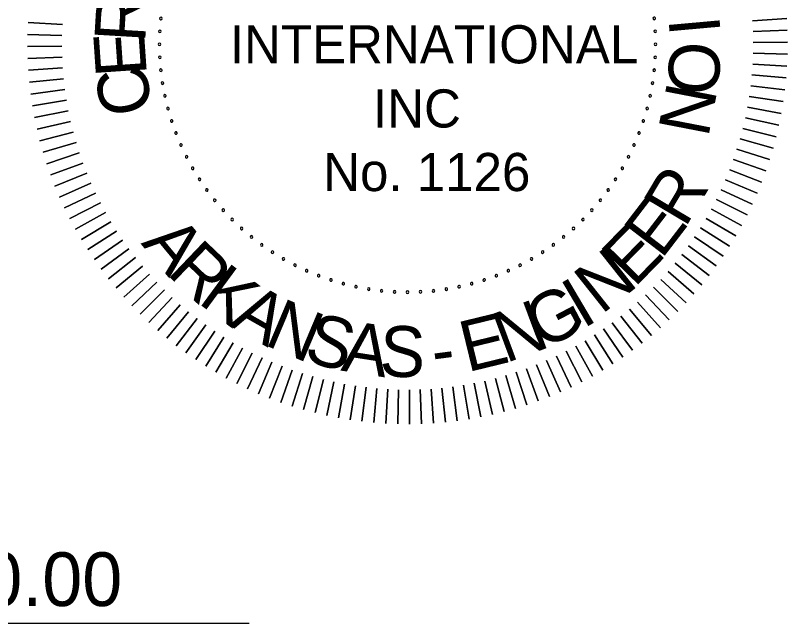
# Model space of a CAD drawing. Extents: x 172 to 3385, y 73 to 2074.
# Drawn here: x 2775.5 to 3028.3, y 337.6 to 536.9 of the extents above; entities that cross this region are included whole.
import ezdxf

# ---------------------------------------------------------------- set-up
doc = ezdxf.new("R2010")
doc.units = 0
doc.layers.add('G-ANNO-TEXT', color=7, linetype='Continuous')
doc.layers.add('R_Border', color=7, linetype='Continuous')

msp = doc.modelspace()

# ---------------------------------------------------------------- linework, layer by layer
at = {"layer": 'G-ANNO-TEXT'}
for points in [[(2790.84, 533.89), (2779.63, 534.53)], [(2779.63, 534.53), (2790.84, 533.89)], [(3028.02, 535.92), (3016.82, 535.15)], [(3016.82, 535.15), (3028.02, 535.92)], [(3028.23, 532.01), (3017.01, 531.6)], [(3017.01, 531.6), (3028.23, 532.01)], [(2790.69, 530.34), (2779.47, 530.63)], [(2779.47, 530.63), (2790.69, 530.34)], [(2790.65, 526.78), (2779.43, 526.72)], [(2779.43, 526.72), (2790.65, 526.78)], [(3028.31, 528.1), (3017.09, 528.04)], [(3017.09, 528.04), (3028.31, 528.1)], [(3028.27, 524.2), (3017.05, 524.49)], [(3017.05, 524.49), (3028.27, 524.2)], [(2790.73, 523.22), (2779.51, 522.81)], [(2779.51, 522.81), (2790.73, 523.22)], [(3028.11, 520.29), (3016.9, 520.93)], [(3016.9, 520.93), (3028.11, 520.29)], [(2790.92, 519.67), (2779.72, 518.91)], [(2779.72, 518.91), (2790.92, 519.67)], [(2791.21, 516.13), (2780.05, 515.01)], [(2780.05, 515.01), (2791.21, 516.13)], [(3027.82, 516.39), (3016.64, 517.38)], [(3016.64, 517.38), (3027.82, 516.39)], [(3027.41, 512.5), (3016.27, 513.85)], [(3016.27, 513.85), (3027.41, 512.5)], [(2791.62, 512.6), (2780.5, 511.13)], [(2780.5, 511.13), (2791.62, 512.6)], [(2792.15, 509.08), (2781.07, 507.26)], [(2781.07, 507.26), (2792.15, 509.08)], [(3026.89, 508.63), (3015.79, 510.32)], [(3015.79, 510.32), (3026.89, 508.63)], [(3026.23, 504.77), (3015.2, 506.82)], [(3015.2, 506.82), (3026.23, 504.77)], [(2792.78, 505.58), (2781.76, 503.41)], [(2781.76, 503.41), (2792.78, 505.58)], [(3025.46, 500.94), (3014.5, 503.33)], [(3014.5, 503.33), (3025.46, 500.94)], [(2793.52, 502.1), (2782.58, 499.59)], [(2782.58, 499.59), (2793.52, 502.1)], [(2794.37, 498.64), (2783.51, 495.79)], [(2783.51, 495.79), (2794.37, 498.64)], [(3024.57, 497.14), (3013.69, 499.87)], [(3013.69, 499.87), (3024.57, 497.14)], [(3023.56, 493.36), (3012.77, 496.43)], [(3012.77, 496.43), (3023.56, 493.36)], [(2795.32, 495.22), (2784.56, 492.03)], [(2784.56, 492.03), (2795.32, 495.22)], [(3022.43, 489.62), (3011.74, 493.03)], [(3011.74, 493.03), (3022.43, 489.62)], [(2796.39, 491.83), (2785.74, 488.3)], [(2785.74, 488.3), (2796.39, 491.83)], [(2797.56, 488.47), (2787.02, 484.61)], [(2787.02, 484.61), (2797.56, 488.47)], [(3021.19, 485.91), (3010.61, 489.65)], [(3010.61, 489.65), (3021.19, 485.91)], [(3019.83, 482.25), (3009.37, 486.32)], [(3009.37, 486.32), (3019.83, 482.25)], [(2798.84, 485.15), (2788.42, 480.96)], [(2788.42, 480.96), (2798.84, 485.15)], [(3018.35, 478.63), (3008.03, 483.03)], [(3008.03, 483.03), (3018.35, 478.63)], [(2800.21, 481.87), (2789.94, 477.35)], [(2789.94, 477.35), (2800.21, 481.87)], [(2801.7, 478.64), (2791.57, 473.8)], [(2791.57, 473.8), (2801.7, 478.64)], [(3016.76, 475.06), (3006.58, 479.78)], [(3006.58, 479.78), (3016.76, 475.06)], [(2803.28, 475.45), (2793.31, 470.3)], [(2793.31, 470.3), (2803.28, 475.45)], [(3015.06, 471.54), (3005.03, 476.57)], [(3005.03, 476.57), (3015.06, 471.54)], [(3013.25, 468.07), (3003.39, 473.42)], [(3003.39, 473.42), (3013.25, 468.07)], [(2804.96, 472.32), (2795.16, 466.85)], [(2795.16, 466.85), (2804.96, 472.32)], [(3011.33, 464.66), (3001.64, 470.32)], [(3001.64, 470.32), (3011.33, 464.66)], [(2806.74, 469.24), (2797.11, 463.47)], [(2797.11, 463.47), (2806.74, 469.24)], [(2808.62, 466.21), (2799.17, 460.15)], [(2799.17, 460.15), (2808.62, 466.21)], [(3009.31, 461.32), (2999.8, 467.28)], [(2999.8, 467.28), (3009.31, 461.32)], [(2810.58, 463.25), (2801.34, 456.89)], [(2801.34, 456.89), (2810.58, 463.25)], [(3007.18, 458.04), (2997.86, 464.3)], [(2997.86, 464.3), (3007.18, 458.04)], [(2812.65, 460.35), (2803.6, 453.71)], [(2803.6, 453.71), (2812.65, 460.35)], [(3004.95, 454.83), (2995.83, 461.37)], [(2995.83, 461.37), (3004.95, 454.83)], [(3002.62, 451.69), (2993.72, 458.52)], [(2993.72, 458.52), (3002.62, 451.69)], [(2814.8, 457.52), (2805.97, 450.59)], [(2805.97, 450.59), (2814.8, 457.52)], [(3000.19, 448.63), (2991.51, 455.73)], [(2991.51, 455.73), (3000.19, 448.63)], [(2817.04, 454.76), (2808.43, 447.56)], [(2808.43, 447.56), (2817.04, 454.76)], [(2997.67, 445.64), (2989.21, 453.01)], [(2989.21, 453.01), (2997.67, 445.64)], [(2819.36, 452.07), (2810.98, 444.6)], [(2810.98, 444.6), (2819.36, 452.07)], [(2995.06, 442.73), (2986.83, 450.37)], [(2986.83, 450.37), (2995.06, 442.73)], [(2821.77, 449.45), (2813.63, 441.72)], [(2813.63, 441.72), (2821.77, 449.45)], [(2992.35, 439.91), (2984.37, 447.8)], [(2984.37, 447.8), (2992.35, 439.91)], [(2824.26, 446.91), (2816.37, 438.93)], [(2816.37, 438.93), (2824.26, 446.91)], [(2989.56, 437.17), (2981.83, 445.31)], [(2981.83, 445.31), (2989.56, 437.17)], [(2826.83, 444.45), (2819.19, 436.22)], [(2819.19, 436.22), (2826.83, 444.45)], [(2986.68, 434.53), (2979.21, 442.9)], [(2979.21, 442.9), (2986.68, 434.53)], [(2822.1, 433.61), (2829.47, 442.07)], [(2829.47, 442.07), (2822.1, 433.61)], [(2983.72, 431.97), (2976.52, 440.58)], [(2976.52, 440.58), (2983.72, 431.97)], [(2825.08, 431.09), (2832.19, 439.77)], [(2832.19, 439.77), (2825.08, 431.09)], [(2828.15, 428.66), (2834.98, 437.57)], [(2834.98, 437.57), (2828.15, 428.66)], [(2980.69, 429.51), (2973.76, 438.34)], [(2973.76, 438.34), (2980.69, 429.51)], [(2831.29, 426.33), (2837.83, 435.45)], [(2837.83, 435.45), (2831.29, 426.33)], [(2977.57, 427.15), (2970.93, 436.19)], [(2970.93, 436.19), (2977.57, 427.15)], [(2834.5, 424.1), (2840.75, 433.42)], [(2840.75, 433.42), (2834.5, 424.1)], [(2974.39, 424.88), (2968.03, 434.13)], [(2968.03, 434.13), (2974.39, 424.88)], [(2837.78, 421.97), (2843.74, 431.48)], [(2843.74, 431.48), (2837.78, 421.97)], [(2967.81, 420.65), (2962.04, 430.28)], [(2962.04, 430.28), (2967.81, 420.65)], [(2971.13, 422.72), (2965.07, 432.16)], [(2965.07, 432.16), (2971.13, 422.72)], [(2841.12, 419.95), (2846.78, 429.64)], [(2846.78, 429.64), (2841.12, 419.95)], [(2844.53, 418.03), (2849.88, 427.89)], [(2849.88, 427.89), (2844.53, 418.03)], [(2964.43, 418.7), (2958.97, 428.5)], [(2958.97, 428.5), (2964.43, 418.7)], [(2847.99, 416.22), (2853.03, 426.25)], [(2853.03, 426.25), (2847.99, 416.22)], [(2957.48, 415.11), (2952.65, 425.24)], [(2952.65, 425.24), (2957.48, 415.11)], [(2960.98, 416.85), (2955.83, 426.82)], [(2955.83, 426.82), (2960.98, 416.85)], [(2851.51, 414.52), (2856.24, 424.7)], [(2856.24, 424.7), (2851.51, 414.52)], [(2855.09, 412.93), (2859.48, 423.26)], [(2859.48, 423.26), (2855.09, 412.93)], [(2950.32, 411.97), (2946.13, 422.38)], [(2946.13, 422.38), (2950.32, 411.97)], [(2953.93, 413.48), (2949.41, 423.76)], [(2949.41, 423.76), (2953.93, 413.48)], [(2858.71, 411.46), (2862.78, 421.91)], [(2862.78, 421.91), (2858.71, 411.46)], [(2862.37, 410.09), (2866.11, 420.67)], [(2866.11, 420.67), (2862.37, 410.09)], [(2942.98, 409.28), (2939.46, 419.93)], [(2939.46, 419.93), (2942.98, 409.28)], [(2946.67, 410.56), (2942.81, 421.1)], [(2942.81, 421.1), (2946.67, 410.56)], [(2866.08, 408.85), (2869.48, 419.54)], [(2869.48, 419.54), (2866.08, 408.85)], [(2869.82, 407.72), (2872.89, 418.51)], [(2872.89, 418.51), (2869.82, 407.72)], [(2873.59, 406.71), (2876.32, 417.59)], [(2876.32, 417.59), (2873.59, 406.71)], [(2935.49, 407.05), (2932.64, 417.91)], [(2932.64, 417.91), (2935.49, 407.05)], [(2939.25, 408.11), (2936.06, 418.87)], [(2936.06, 418.87), (2939.25, 408.11)], [(2877.4, 405.82), (2879.79, 416.78)], [(2879.79, 416.78), (2877.4, 405.82)], [(2881.23, 405.05), (2883.27, 416.08)], [(2883.27, 416.08), (2881.23, 405.05)], [(2885.09, 404.4), (2886.78, 415.49)], [(2886.78, 415.49), (2885.09, 404.4)], [(2888.96, 403.87), (2890.31, 415.01)], [(2890.31, 415.01), (2888.96, 403.87)], [(2916.27, 403.59), (2915.15, 414.76)], [(2915.15, 414.76), (2916.27, 403.59)], [(2920.15, 404.04), (2918.69, 415.17)], [(2918.69, 415.17), (2920.15, 404.04)], [(2924.02, 404.61), (2922.2, 415.69)], [(2922.2, 415.69), (2924.02, 404.61)], [(2927.87, 405.31), (2925.7, 416.32)], [(2925.7, 416.32), (2927.87, 405.31)], [(2931.69, 406.12), (2929.18, 417.06)], [(2929.18, 417.06), (2931.69, 406.12)], [(2892.85, 403.46), (2893.84, 414.64)], [(2893.84, 414.64), (2892.85, 403.46)], [(2896.75, 403.17), (2897.39, 414.38)], [(2897.39, 414.38), (2896.75, 403.17)], [(2900.65, 403.01), (2900.94, 414.23)], [(2900.94, 414.23), (2900.65, 403.01)], [(2904.56, 402.97), (2904.5, 414.19)], [(2904.5, 414.19), (2904.56, 402.97)], [(2908.47, 403.06), (2908.06, 414.27)], [(2908.06, 414.27), (2908.47, 403.06)], [(2912.38, 403.26), (2911.61, 414.46)], [(2911.61, 414.46), (2912.38, 403.26)]]:
    msp.add_lwpolyline(points, dxfattribs=at)
for centre, start, end in [((2823.1, 535.9), 84, 264), ((2823.1, 535.9), 264, 84), ((2984.64, 535.9), 96, 276), ((2984.64, 535.9), 276, 96), ((2822.77, 531.66), 87, 267), ((2822.77, 531.66), 267, 87), ((2984.97, 531.66), 93, 273), ((2984.97, 531.66), 273, 93), ((2822.65, 527.41), 90, 270), ((2822.65, 527.41), 270, 90), ((2985.08, 527.41), 90, 270), ((2985.08, 527.41), 270, 90), ((2822.77, 523.16), 93, 273), ((2822.77, 523.16), 273, 93), ((2984.97, 523.16), 87, 267), ((2984.97, 523.16), 267, 87), ((2823.1, 518.92), 96, 276), ((2823.1, 518.92), 276, 96), ((2984.64, 518.92), 84, 264), ((2984.64, 518.92), 264, 84), ((2823.65, 514.71), 99, 279), ((2823.65, 514.71), 279, 99), ((2984.08, 514.71), 81, 261), ((2984.08, 514.71), 261, 81), ((2824.43, 510.53), 102, 282), ((2824.43, 510.53), 282, 102), ((2983.31, 510.53), 78, 258), ((2983.31, 510.53), 258, 78), ((2825.42, 506.39), 105, 285), ((2825.42, 506.39), 285, 105), ((2982.32, 506.39), 75, 255), ((2982.32, 506.39), 255, 75), ((2826.63, 502.31), 108, 288), ((2826.63, 502.31), 288, 108), ((2981.11, 502.31), 72, 252), ((2981.11, 502.31), 252, 72), ((2828.05, 498.31), 111, 291), ((2828.05, 498.31), 291, 111), ((2979.69, 498.31), 69, 249), ((2979.69, 498.31), 249, 69), ((2829.68, 494.38), 114, 294), ((2829.68, 494.38), 294, 114), ((2978.06, 494.38), 66, 246), ((2978.06, 494.38), 246, 66), ((2831.51, 490.54), 117, 297), ((2831.51, 490.54), 297, 117), ((2976.23, 490.54), 63, 243), ((2976.23, 490.54), 243, 63), ((2833.54, 486.8), 120, 300), ((2833.54, 486.8), 300, 120), ((2974.2, 486.8), 60, 240), ((2974.2, 486.8), 240, 60), ((2835.76, 483.18), 123, 303), ((2835.76, 483.18), 303, 123), ((2971.98, 483.18), 57, 237), ((2971.98, 483.18), 237, 57), ((2838.17, 479.67), 126, 306), ((2838.17, 479.67), 306, 126), ((2969.57, 479.67), 54, 234), ((2969.57, 479.67), 234, 54), ((2840.75, 476.3), 129, 309), ((2840.75, 476.3), 309, 129), ((2966.99, 476.3), 51, 231), ((2966.99, 476.3), 231, 51), ((2843.52, 473.07), 132, 312), ((2843.52, 473.07), 312, 132), ((2964.22, 473.07), 48, 228), ((2964.22, 473.07), 228, 48), ((2846.44, 469.98), 135, 315), ((2846.44, 469.98), 315, 135), ((2961.3, 469.98), 45, 225), ((2961.3, 469.98), 225, 45), ((2849.53, 467.06), 138, 318), ((2849.53, 467.06), 318, 138), ((2958.21, 467.06), 42, 222), ((2958.21, 467.06), 222, 42), ((2852.76, 464.3), 141, 321), ((2852.76, 464.3), 321, 141), ((2954.98, 464.3), 39, 219), ((2954.98, 464.3), 219, 39), ((2856.13, 461.71), 144, 324), ((2856.13, 461.71), 324, 144), ((2951.61, 461.71), 36, 216), ((2951.61, 461.71), 216, 36), ((2859.64, 459.3), 147, 327), ((2859.64, 459.3), 327, 147), ((2948.1, 459.3), 33, 213), ((2948.1, 459.3), 213, 33), ((2863.26, 457.08), 150, 330), ((2863.26, 457.08), 330, 150), ((2867, 455.05), 153, 333), ((2867, 455.05), 333, 153), ((2940.74, 455.05), 27, 207), ((2940.74, 455.05), 207, 27), ((2944.48, 457.08), 30, 210), ((2944.48, 457.08), 210, 30), ((2870.84, 453.22), 156, 336), ((2870.84, 453.22), 336, 156), ((2936.9, 453.22), 24, 204), ((2936.9, 453.22), 204, 24), ((2874.76, 451.59), 159, 339), ((2874.76, 451.59), 339, 159), ((2878.77, 450.17), 162, 342), ((2878.77, 450.17), 342, 162), ((2928.97, 450.17), 18, 198), ((2928.97, 450.17), 198, 18), ((2932.97, 451.59), 21, 201), ((2932.97, 451.59), 201, 21), ((2882.85, 448.96), 165, 345), ((2882.85, 448.96), 345, 165), ((2886.98, 447.97), 168, 348), ((2886.98, 447.97), 348, 168), ((2891.16, 447.2), 351, 171), ((2916.57, 447.2), 9, 189), ((2920.76, 447.97), 12, 192), ((2920.76, 447.97), 192, 12), ((2924.89, 448.96), 15, 195), ((2924.89, 448.96), 195, 15), ((2891.16, 447.2), 171, 351), ((2895.38, 446.64), 174, 354), ((2895.38, 446.64), 354, 174), ((2899.62, 446.31), 357, 177), ((2899.62, 446.31), 177, 357), ((2903.87, 446.2), 0, 180), ((2903.87, 446.2), 180, 0), ((2908.12, 446.31), 3, 183), ((2908.12, 446.31), 183, 3), ((2912.36, 446.64), 6, 186), ((2912.36, 446.64), 186, 6), ((2916.57, 447.2), 189, 9)]:
    msp.add_arc(centre, 0.417, start, end, dxfattribs=at)
at = {"layer": 'R_Border'}
msp.add_lwpolyline([(2851.99, 337.59), (2633.63, 337.59), (1993.94, 689.42), (2018.51, 652.93), (2030.6, 674)], dxfattribs=at)

# ---------------------------------------------------------------- texts
at = {"layer": 'G-ANNO-TEXT'}
for s, rotation, p in [('R', 86.6268, (2817.92, 527.78)), ('I', 275.1216, (2989.28, 535.82)), ('E', 93.9203, (2818.54, 517.37)), ('O', 267.0743, (2989.86, 528.66)), ('C', 101.2137, (2820.67, 505.78)), ('N', 259.0269, (2988.99, 515.55)), ('R', 59.2262, (2994.74, 466.97)), ('E', 52.4765, (2987, 456.71)), ('A', 309.5859, (2816.4, 462.15)), ('E', 45.7268, (2978.12, 447.43)), ('R', 316.3356, (2824.68, 452.32)), ('N', 38.4196, (2967.34, 438.64)), ('K', 323.6428, (2834.88, 442.86)), ('I', 30.5495, (2961.29, 434.04)), ('A', 330.3925, (2845.29, 435.33)), ('G', 27.7404, (2948.11, 427.05)), ('N', 337.1422, (2856.52, 429.09)), ('N', 20.4332, (2935.98, 422.84)), ('S', 344.4494, (2869.41, 423.86)), ('E', 13.6835, (2923.41, 419.9)), ('A', 351.1991, (2881.82, 420.53)), ('S', 357.9489, (2894.53, 418.68)), ('-', 7.5077, (2912.72, 418.64))]:
    msp.add_text(s, height=16.67, rotation=rotation, dxfattribs=at).set_placement(p)
for s, height, p in [(' INTERNATIONAL', 12.5016, (2841.03, 521.17)), ('INC', 12.502, (2892.55, 500.14)), (' No. 1126', 12.502, (2871.6, 479.31))]:
    msp.add_text(s, height=height, dxfattribs=at).set_placement(p)
at = {"layer": 'R_Border'}
msp.add_text('STA. 298+00.00', height=17.61, dxfattribs=at).set_placement((2639.6, 343.33))

doc.saveas('drawing.dxf')
